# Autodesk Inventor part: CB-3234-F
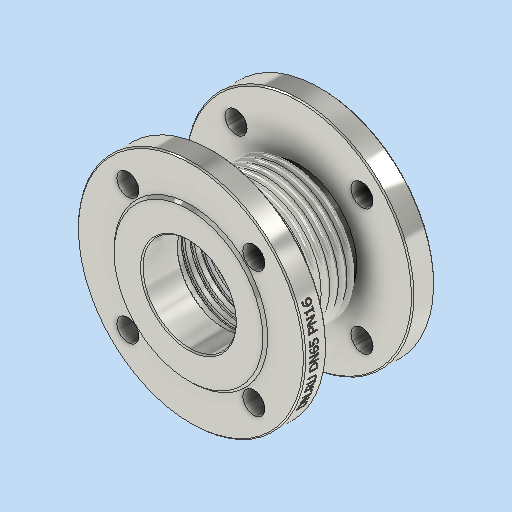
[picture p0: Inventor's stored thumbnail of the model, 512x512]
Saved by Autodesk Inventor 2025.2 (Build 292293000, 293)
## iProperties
Company: DN.RU
Created: 2026-04
Part Number: CB-3234-F
Material: Типовые
Document SubType Name: Modeling
Designer: DN.RU
Density: 6.4251 g/cm^3
Appearance: По умолчанию
Description: D140-02114
Mass: 6000 g
Surface Area: 2646.29 cm^2
Volume: 933.837 cm^3
Author: DN.RU
Title: Компенсатор сильфонный осевой DN.ru Ду65 Ру16
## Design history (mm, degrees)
sketch "Эскиз1"
  geometry: L1 (0, 0)-(0, -55); L2 (44, -55)-(44, 0); L3 (44, 0)-(0, 0); L4 (44, 0)-(44, -3.5); L5 (36, -3.5)-(52, -3.5); L6 (36, -6)-(52, -6); L7 (52, -1)-(36, -1); L8 (52, -4)-(36, -4); L9 (36, -3)-(52, -3); L10 (52, -8)-(36, -8); L11 (36, -10)-(52, -10); L12 (36, -10.5)-(52, -10.5); L13 (36, -13)-(52, -13); L14 (52, -11)-(36, -11); L15 (52, -15)-(36, -15); L16 (36, -17)-(52, -17); L17 (36, -17.5)-(52, -17.5); L18 (36, -20)-(52, -20); L19 (52, -18)-(36, -18); L20 (52, -22)-(36, -22); L21 (36, -24)-(52, -24); L22 (36, -24.5)-(52, -24.5); L23 (36, -27)-(52, -27); L24 (52, -25)-(36, -25); L25 (0, -55)-(44, -55); L26 (44, -55)-(38, -55); L27 (44, -22)-(42, -22); L28 (38, -55)-(38, -25); L29 (44, -24)-(42, -24); L30 (42, -24)-(42, -18); L31 (44, -17)-(42, -17); L32 (42, -17)-(42, -11); L33 (44, -10)-(42, -10); L34 (42, -10)-(42, -4); L35 (44, -3)-(43, -3); L36 (43, -3)-(42, 0); L37 (0, -55)-(0, -35); L38 (0, -35)-(92.5, -35); L39 (92.5, -35)-(92.5, -55); L40 (92.5, -55)-(0, -55); L41 (44, -35)-(44, -45); L42 (44, -45)-(47, -45); L43 (47, -45)-(47, -35); L44 (47, -35)-(44, -35); A1 r 2.5 centre (36, -3.5) between (36, -1) and (36, -6); A2 r 2.5 centre (52, -3.5) between (52, -6) and (52, -1); A3 r 0.5 centre (36, -3.5) between (36, -3) and (36, -4); A4 r 0.5 centre (52, -3.5) between (52, -4) and (52, -3); A5 r 0.5 centre (36, -10.5) between (36, -10) and (36, -11); A6 r 2.5 centre (36, -10.5) between (36, -8) and (36, -13); A7 r 0.5 centre (52, -10.5) between (52, -11) and (52, -10); A8 r 2.5 centre (52, -10.5) between (52, -13) and (52, -8); A9 r 0.5 centre (36, -17.5) between (36, -17) and (36, -18); A10 r 2.5 centre (36, -17.5) between (36, -15) and (36, -20); A11 r 0.5 centre (52, -17.5) between (52, -18) and (52, -17); A12 r 2.5 centre (52, -17.5) between (52, -20) and (52, -15); A13 r 0.5 centre (36, -24.5) between (36, -24) and (36, -25); A14 r 2.5 centre (36, -24.5) between (36, -22) and (36, -27); A15 r 0.5 centre (52, -24.5) between (52, -25) and (52, -24); A16 r 2.5 centre (52, -24.5) between (52, -27) and (52, -22); 20 further points
  constraints: 96 end point, 32 point on circle, 19 point on line, 16 centre point, 7 parallel, 7 perpendicular, 6 midpoint, 4 tangent, 2 vertical, 1 horizontal, 69 other
  dimensions: "d0" = 55 distance of L1.start L1.end; "d3" = 3.5 distance of L2.end L4.end; "d4" = 8 distance of L4.end L5.end; "d5" = 5 diameter of A2; "d6" = 2 distance between parallel lines of L6 L8; "d9" = 7 distance of L4.end point (44, -10.5); "d15" = 2 distance of L27.start L27.end; "d16" = 2 distance of L29.start L29.end; "d17" = 2 distance of L31.start L31.end; "d18" = 2 distance of L33.start L33.end; "d19" = 1 distance of L35.start L35.end; "d27" = 38 distance between parallel lines of L1 L28; "d28" = 6 distance between parallel lines of L2 L28; "d29" = 20 distance of L1.end L37.end; "d30" = 92.5 distance of L37.end L38.end; "d31" = 10 distance of L41.start L41.end; "d32" = 3 distance of L42.end L41.end
revolve "Вращение1" sketch "Эскиз1" stored, may be unused: angle "d20" = 360 deg
sketch "Эскиз3" dims "d33" = 145
  geometry: L1 (0, 0)-(54.414, 54.414); L2 (0, 0)-(76.954, 0); C1 r 9 at (51.265, 51.265); C2 r 9 at (-51.265, 51.265); C3 r 9 at (-51.265, -51.265); C4 r 9 at (51.265, -51.265); C5 r 38 at (0, 0) reference; C6 r 62.5 at (0, 0); C7 r 92.5 at (0, 0) reference; 1 further point
  constraints: 5 centre point, 4 end point, 2 coincident, 1 equal length, 1 horizontal, 1 point on line, 12 other
  dimensions: "d34" = 45 deg angle of L2 L1; "d35" = 18 diameter of C1; "d38" = 360 deg dimension on point (0, 0) C1.centre (derived); "d40" = 125 diameter of C6
  node "Эскиз — круговой массив1" dims "d38" = 360 deg (derived)
extrude "Выдавливание1" cut sketch "Эскиз3" stored distance "d41" = 10; taper "d42" = 0 deg
extrude "Выдавливание2" cut sketch "Эскиз3" distance "d43" = 2; taper "d44" = 0 deg
chamfer "Фаска2" distance "d45" = 2; stored, may be unused: second distance "d46" = 2, angle "d47" = 45 deg
chamfer "Фаска3" distance "d48" = 1; stored, may be unused: second distance "d49" = 2, angle "d50" = 45 deg
mirror "Зеркальное отражение2"
fillet "Сопряжение2" dims "d51" = 1
node "РабПлоскость2"
sketch "Эскиз4"
  geometry: L1 (-44.383, 3.589)-(46.395, 3.589); L2 (46.395, 3.589)-(46.395, 0.413); L3 (46.395, 0.413)-(-44.383, 0.413); L4 (-44.383, 0.413)-(-44.383, 3.589); 1 further point
  constraints: 2 other
feature "Рельеф2" sketch "Эскиз4" dims "d52" = 0.1, "d53" = 0
node "Твердое тело1"
node "Эскиз — прямоугольный массив1" dims "d9" = 7, "d12" = 10
